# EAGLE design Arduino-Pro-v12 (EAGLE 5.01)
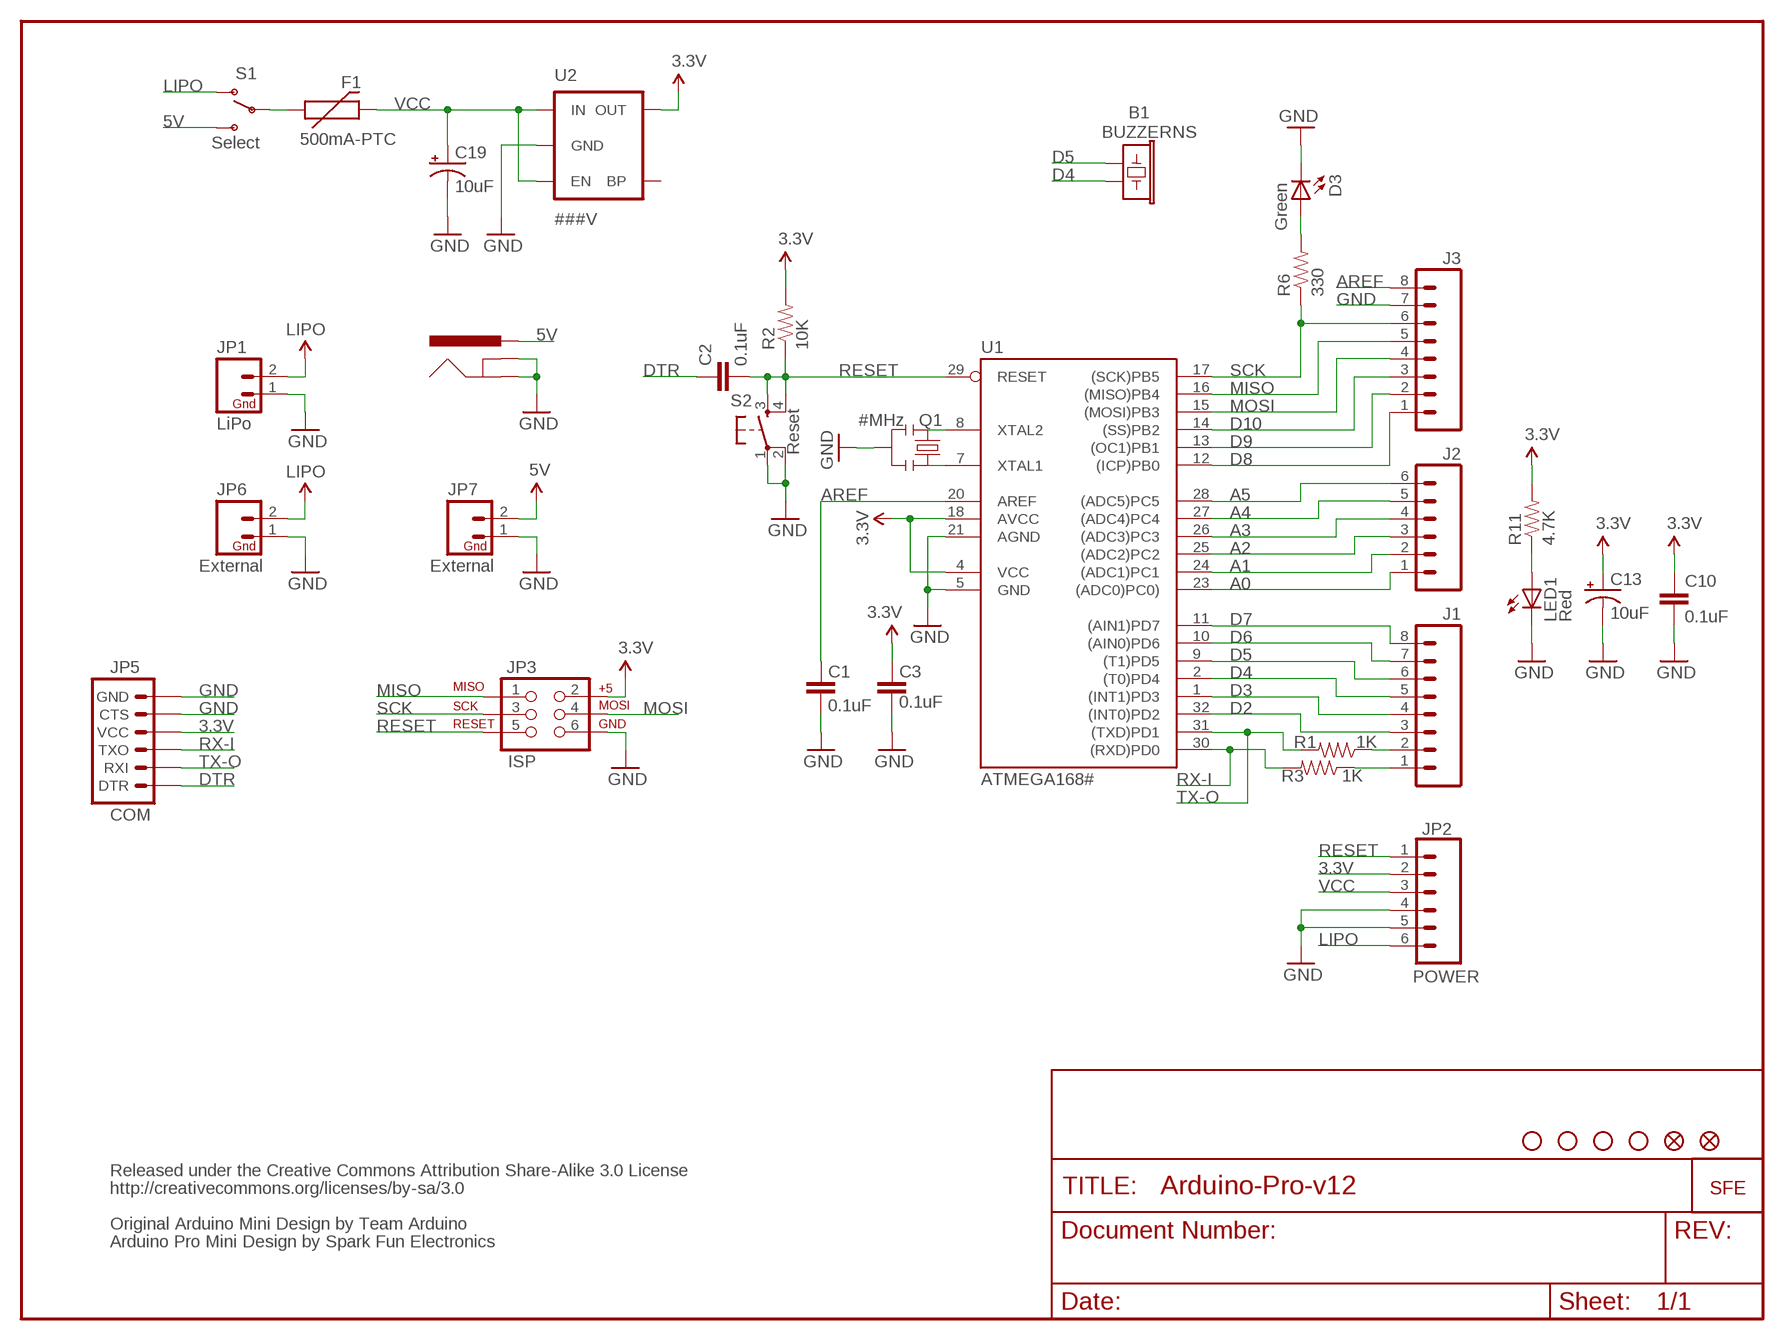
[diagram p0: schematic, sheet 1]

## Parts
B1  BUZZERNS  [BUZZER-12MM-NS]
C1  0.1uF  CAP0402  [C0402]
C2  0.1uF  CAP0402  [C0402]
C3  0.1uF  CAP0402  [C0402]
C10  0.1uF  CAP0402  [C0402]
C13  10uF  CAP_POL1206  [EIA3216]
C19  10uF  CAP_POL1206  [EIA3216]
D3  Green  LED0603  [LED-0603]
F1  500mA-PTC  PTCSMD  [PTC-1206]
J1  M08  [1X08]
J2  M06SIP  [1X06]
J3  M08  [1X08]
JP1  LiPo  M02-JST-2MM-SMT  [S2B-PH]
JP2  POWER  M06SIP  [1X06]
JP3  ISP  AVR_SPI_PRG_6PTH  [2X3]
JP4  Power Jack  POWER_JACKPTH  [POWER_JACK_PTH]
JP5  COM  ARDUINO_SERIAL_PROGRAMPTH  [1X06]
JP6  External  M02PTH  [1X02]
JP7  External  M02PTH  [1X02]
LED1  Red  LED0603  [LED-0603]
Q1  #MHz  RESONATORSMD  [RESONATOR-SMD]
R1  1K  RESISTOR0402  [C0402]
R2  10K  RESISTOR0402  [C0402]
R3  1K  RESISTOR0402  [C0402]
R6  330  RESISTOR0402  [C0402]
R11  4.7K  RESISTOR0402  [C0402]
S1  Select  SWITCH-SPSTSMD2  [SWITCH-SPST-SMD]
S2  Reset  TAC_SWITCHSND  [TACTILE_SWITCH_SMD]
U1  ATMEGA168#  AT90S4433A  [TQFP32-08]
U2  ###V  V_REG_LDOSMD  [SOT23-5]
U$1  STAND-OFF  [STAND-OFF]
U$2  FIDUCIAL1X2  [FIDUCIAL-1X2]
U$3  STAND-OFF  [STAND-OFF]
U$4  FIDUCIAL1X2  [FIDUCIAL-1X2]
U$9  STAND-OFF  [STAND-OFF]
U$10  STAND-OFF  [STAND-OFF]
U$11  LOGO-SFENEW  [SFE-NEW-WEBLOGO]

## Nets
3.3V: C3.2 C10.1 C13.A(+) JP2.2 JP3.2 JP5.4(VCC) R2.2 R11.2 U1.4(VCC) U1.18(AVCC) U2.5(OUT)
5V [vcc]: JP4.PWR JP7.2 S1.3(S)
A0: J2.1 U1.23((ADC0)PC0))
A1: J2.2 U1.24((ADC1)PC1)
A2: J2.3 U1.25((ADC2)PC2)
A3: J2.4 U1.26((ADC3)PC3)
A4: J2.5 U1.27((ADC4)PC4)
A5: J2.6 U1.28((ADC5)PC5)
AREF: C1.2 J3.8 U1.20(AREF)
D2: J1.3 U1.32((INT0)PD2)
D3: J1.4 U1.1((INT1)PD3)
D4: B1.- J1.5 U1.2((T0)PD4)
D5: B1.+ J1.6 U1.9((T1)PD5)
D6: J1.7 U1.10((AIN0)PD6)
D7: J1.8 U1.11((AIN1)PD7)
D8: J3.1 U1.12((ICP)PB0)
D9: J3.2 U1.13((OC1)PB1)
D10: J3.3 U1.14((SS)PB2)
DTR: C2.1 JP5.1(DTR)
GND [vcc]: C1.1 C3.1 C10.2 C13.C(-) C19.C(-) D3.C J3.7 JP1.1 JP2.4 JP2.5 JP3.6 JP4.GND JP4.GNDBREAK JP5.5(CTS) JP5.6(GND) JP6.1 JP7.1 LED1.C Q1.2 S2.1 S2.2 U1.5(GND) U1.21(AGND) U2.2(GND)
LIPO: JP1.2 JP2.6 JP6.2 S1.1(O)
MISO: J3.5 JP3.1 U1.16((MISO)PB4)
MOSI: J3.4 JP3.4 U1.15((MOSI)PB3)
N$3: Q1.1 U1.8(XTAL2)
N$4: Q1.3 U1.7(XTAL1)
N$7: D3.A R6.2
N$25: F1.1 S1.2(P)
N$38: LED1.A R11.1
RESET: C2.2 JP2.1 JP3.5 R2.1 S2.3 S2.4 U1.29(RESET)
RX-I: JP5.3(TXO) R3.2 U1.30((RXD)PD0)
RX-IP: J1.2 R1.1
SCK: J3.6 JP3.3 R6.1 U1.17((SCK)PB5)
TX-O: JP5.2(RXI) R1.2 U1.31((TXD)PD1)
TX-OP: J1.1 R3.1
VCC [vcc]: C19.A(+) F1.2 JP2.3 U2.1(IN) U2.3(EN)
Unconnected: U2.4(BP)

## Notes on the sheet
- Released under the Creative Commons Attribution Share-Alike 3.0 License
- http://creativecommons.org/licenses/by-sa/3.0
- Original Arduino Mini Design by Team Arduino
- Arduino Pro Mini Design by Spark Fun Electronics

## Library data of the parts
B1 = SparkFun:BUZZER: Buzzer 12mm
C1-C3 C10 = SparkFun:CAP: Capacitor
C13 C19 = SparkFun:CAP_POL: Capacitor Polarized
D3 LED1 = SparkFun:LED: LEDs
F1 = SparkFun:PTC: Resettable Fuse PTC
J1 J3 = SparkFun:M08: Header 8 Standard 8-pin 0.1" header. Use with straight break away headers (SKU : PRT-00116), right angle break away headers (PRT-00553), swiss pins (PRT-00743), machine pins (PRT-00117), and female headers (PRT-00115).
J2 JP2 = SparkFun:M06: Header 6 Standard 6-pin 0.1" header. Use with straight break away headers (SKU : PRT-00116), right angle break away headers (PRT-00553), swiss pins (PRT-00743), machine pins (PRT-00117), and female headers (PRT-00115). Molex polarized connector foot print use with SKU : PRT-08094 with associated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
JP1 JP6 JP7 = SparkFun:M02: Header 2
JP3 = SparkFun:AVR_SPI_PRG_6: AVR ISP 6 Pin This is the reduced ISP connector for AVR programming. Common on Arduino. This footprint will take up less PCB space and can be used with a 10-pin to 6-pin adapter such as SKU: BOB-08508
JP4 = SparkFun:POWER_JACK: Power Jack This is the standard 5.5mm barrel jack for power. The PTH is the most common, proven, reliable, footprint. All others are experimental. The Slot footprint only works if the mill layer is transmitted to the PCB fab house so be warned. Spark Fun Electronics SKU : PRT-00119. Mating wall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
JP5 = SparkFun:ARDUINO_SERIAL_PROGRAM
Q1 = SparkFun:RESONATOR: Resonator Small SMD resonator. This is the itty bitty 10/20MHz resonators with built in caps. CSTCE10M0G55 and CSTCE20M0V53. Footprint has been reviewed closely but hasn't been tested yet.
R1-R3 R6 R11 = SparkFun:RESISTOR: Resistor
S1 = SparkFun:SWITCH-SPST: SPST Switch Simple slide switch. Spark Fun Electronics SKU : COM-00102
S2 = SparkFun:TAC_SWITCH: Momentary Switch Button commonly used for reset or general input. Spark Fun Electronics SKU : COM-00097
U1 = atmel:AT90S4433: MICROCONTROLLER 4 Kbytes FLASH 128 bytes SRAM 256 bytes EEPROM UART 6-channel 10 bit ADC
U2 = SparkFun:V_REG_LDO: Voltage Regulator LDO Standard 150mA LDO voltage regulator in SOT-23 layout. Micrel part MIC5205. BP (by-pass) pin is used to lower output noise with 470pF cap.
U$1 U$3 U$9 U$10 = SparkFun:STAND-OFF: Stand Off
U$2 U$4 = SparkFun:FIDUCIAL: Fiducial Alignment Points
U$11 = SparkFun:LOGO-SFE: Spark Fun Electronics PCB Logo

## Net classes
0 default: width 0.203 mm
1 vcc: width 0.254 mm

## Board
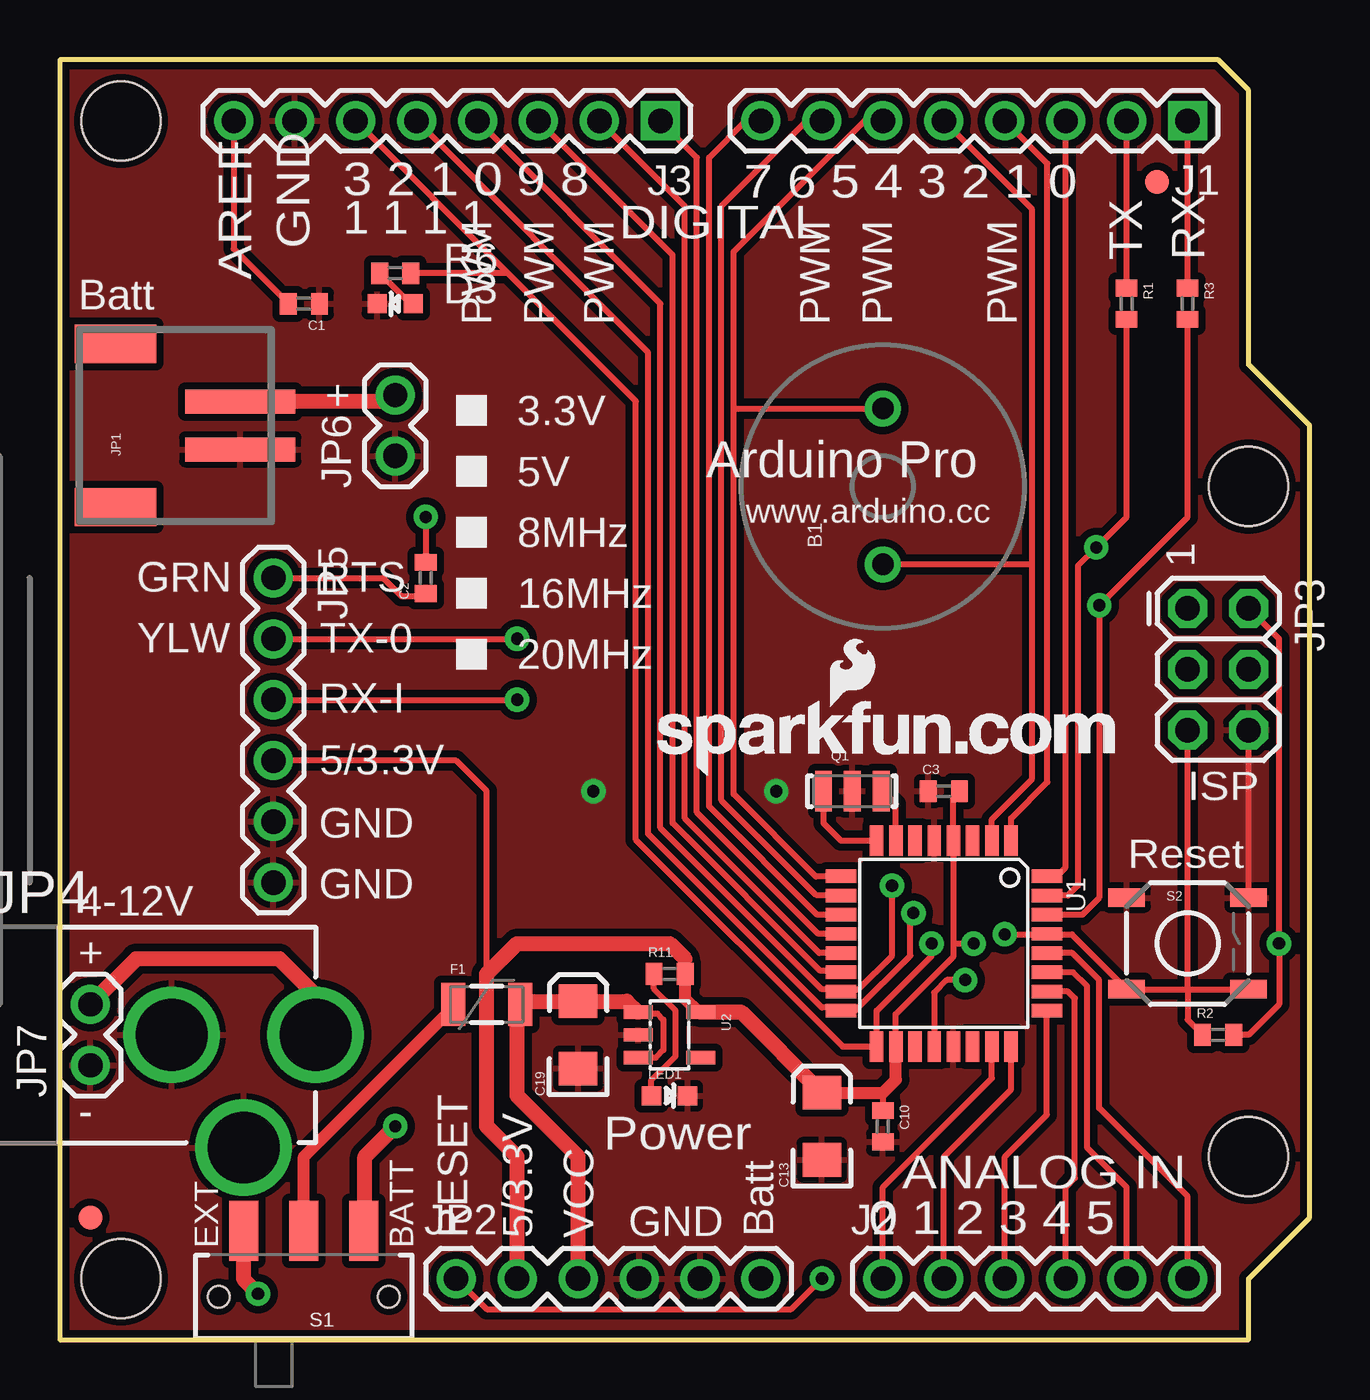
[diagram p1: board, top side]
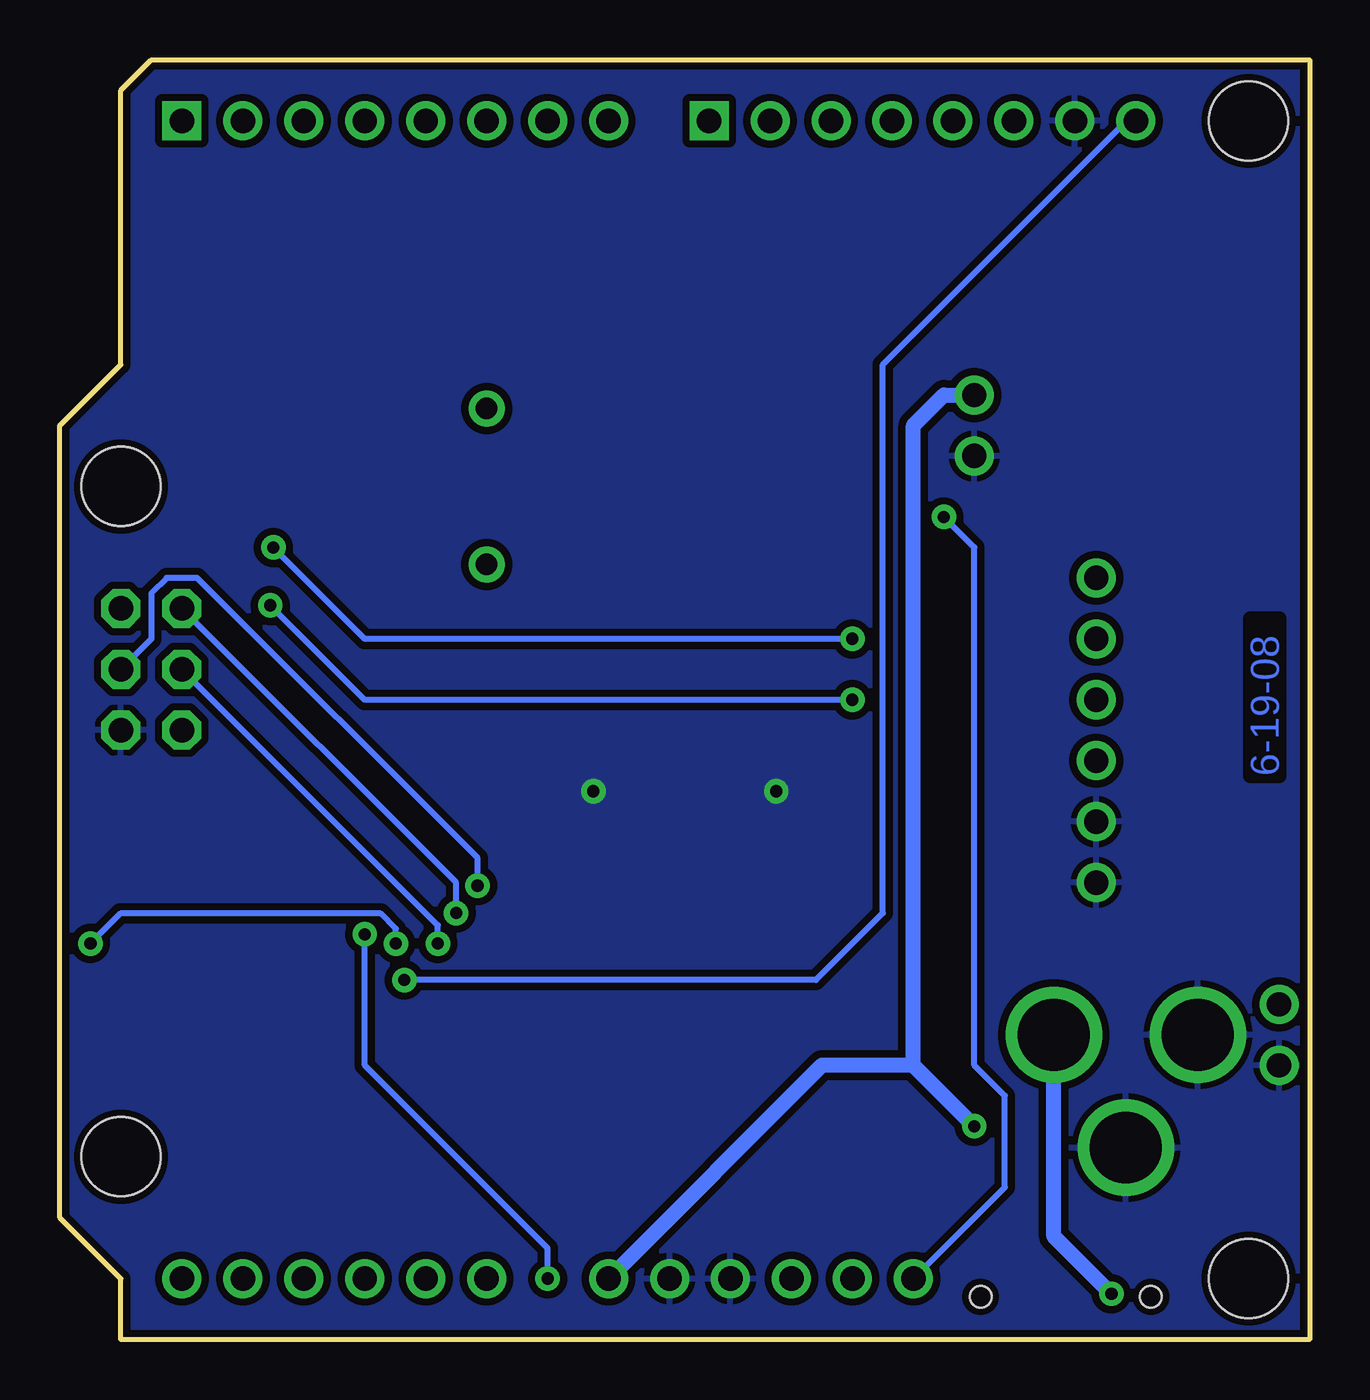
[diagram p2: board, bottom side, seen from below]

Size 52.07 x 53.34 mm. Coordinates in mm from the lower left corner, seen from the top.
Outline: 0,53.34 0,0 49.53,0 49.53,2.54 52.07,5.08 52.07,38.1 49.53,40.64 49.53,52.07 48.26,53.34 0,53.34
Copper layers (1*16): Top 0.035mm / dielectric 1.5mm / Bottom 0.035mm
Design rules "SparkFun": minimum track width 8mil, minimum drill 20mil, track to track 8mil, track to pad 8mil, pad to pad 8mil, via to via 8mil, smd to smd 8mil, copper to edge 10mil, drill to drill 8mil, minimum pad ring 12mil, minimum via ring 10mil, stop-mask expansion 4mil, vias tented up to drill 20mil, thermal gap 10mil

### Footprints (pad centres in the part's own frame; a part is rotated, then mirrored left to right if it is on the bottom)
BUZZER-12MM-NS = drill 0.9 round: + 3.25,0; - -3.25,0
C0402 = smd 0.7 x 0.9: 1 -0.65,0; 2 0.65,0
EIA3216 = smd 1.4 x 1.6: A 1.4,0; C -1.4,0
LED-0603 = smd 0.8 x 0.8: A 0,-0.75; C 0,0.75
PTC-1206 = smd 1 x 1.8: 1 -1.4,0; 2 1.4,0
1X08 = drill 1.016 square: 1 0,0 | drill 1.016 round: 2 2.54,0; 3 5.08,0; 4 7.62,0; 5 10.16,0; 6 12.7,0; 7 15.24,0; 8 17.78,0
1X06 = drill 1.016 round: 1 0,0; 2 2.54,0; 3 5.08,0; 4 7.62,0; 5 10.16,0; 6 12.7,0
S2B-PH = smd 1 x 4.6: 1 -1,-3.7; 2 1,-3.7 | smd 1.6 x 3.4: P$1 -3.4,1.5; P$2 3.4,1.5
2X3 = drill 1.016 octagon: 1 0,0; 2 0,2.54; 3 2.54,0; 4 2.54,2.54; 5 5.08,0; 6 5.08,2.54
POWER_JACK_PTH = drill 2.997 round: GND 0,7.7; GNDBREAK 4.7,10.7; PWR 0,13.7
1X02 = drill 1.016 round: 1 0,0; 2 2.54,0
RESONATOR-SMD = smd 0.7 x 1.7: 1 -1.2,0; 2 0,0; 3 1.2,0
SWITCH-SPST-SMD = smd 1.2 x 2.5: 1 -2.5,-2.75; 2 0,-2.75; 3 2.5,-2.75 | hole 0.9: -3.55,0; 3.55,0
TACTILE_SWITCH_SMD = smd 1.524 x 0.762: 1 -2.54,1.905; 2 2.54,1.905; 3 -2.54,-1.905; 4 2.54,-1.905
TQFP32-08 = smd 1.27 x 0.559: 1 -4.293,2.8; 2 -4.293,2; 3 -4.293,1.2; 4 -4.293,0.4; 5 -4.293,-0.4; 6 -4.293,-1.2; 7 -4.293,-2; 8 -4.293,-2.8; 17 4.293,-2.8; 18 4.293,-2; 19 4.293,-1.2; 20 4.293,-0.4; 21 4.293,0.4; 22 4.293,1.2; 23 4.293,2; 24 4.293,2.8 | smd 0.559 x 1.27: 9 -2.8,-4.293; 10 -2,-4.293; 11 -1.2,-4.293; 12 -0.4,-4.293; 13 0.4,-4.293; 14 1.2,-4.293; 15 2,-4.293; 16 2.8,-4.293; 25 2.8,4.293; 26 2,4.293; 27 1.2,4.293; 28 0.4,4.293; 29 -0.4,4.293; 30 -1.2,4.293; 31 -2,4.293; 32 -2.8,4.293
SOT23-5 = smd 0.55 x 1.2: 1 -0.95,-1.3; 2 0,-1.3; 3 0.95,-1.3; 4 0.95,1.3; 5 -0.95,1.3
STAND-OFF = hole 3.302: 0,0
FIDUCIAL-1X2 = smd 1 x 1: 1 0,0

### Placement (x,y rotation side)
B1  34.29,35.56 90 top
C1  10.16,43.18 180 top
C2  15.24,31.75 90 top
C3  36.83,22.86 0 top
C10  34.29,8.89 270 top
C13  31.75,8.89 90 top
C19  21.59,12.7 90 top
D3  13.97,43.18 90 top
F1  17.78,13.97 0 top
J1  46.99,50.8 180 top
J2  34.29,2.54 0 top
J3  25.02,50.8 180 top
JP1  3.81,38.1 90 top
JP2  16.51,2.54 0 top
JP3  46.99,30.48 270 top
JP4  -3.05,12.7 270 top
JP5  8.89,31.75 270 top
JP6  13.97,36.83 90 top
JP7  1.27,11.43 90 top
LED1  25.4,10.16 270 top
Q1  33.02,22.86 0 top
R1  44.45,43.18 270 top
R2  48.26,12.7 0 top
R3  46.99,43.18 270 top
R6  13.97,44.45 180 top
R11  25.4,15.24 0 top
S1  10.16,1.78 180 top
S2  46.99,16.51 0 top
U1  36.83,16.51 270 top
U2  25.4,12.7 270 top
U$1  2.54,50.8 0 top
U$2  1.27,5.08 0 top
U$3  2.54,2.54 0 top
U$4  45.72,48.26 0 top
U$9  49.53,35.56 0 top
U$10  49.53,7.62 0 top
U$11  24.89,23.5 0 top

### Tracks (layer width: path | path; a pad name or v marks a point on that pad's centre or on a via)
3.3V  (via drill 0.51)
  Top 0.254: 34.29,10.29 C10.1 | C13.A 31.75,10.16 | 26.54,13.59 26.6,13.65 26.61,13.65 U2.5 | U1.18 34.82,13.56 37.24,15.98 37.24,16.51 | U1.4 37.24,20.9 | U1.4 37.23,22.57 37.52,22.86 C3.2 | 37.24,16.51 U1.4 | JP3.2 50.8,29.21 v50.8,16.51 50.8,13.97 49.53,12.7 R2.2 | 37.24,16.51 v38.08,16.51 | JP5.4 16.51,24.13 17.78,22.86 17.78,15.24
  Top 0.508: U1.18 34.83,10.83 34.29,10.29 31.88,10.29 | 26.05,15.86 R11.2 26.04,15.24 26.04,14.22 26.61,13.65
  Top 0.635: U2.5 28.39,13.65 C13.A 31.87,10.29 31.88,10.29 | 26.05,15.86 25.4,16.51 19.05,16.51 17.78,15.24 17.78,8.89 19.05,7.62 JP2.2
  Bottom 0.254: v38.08,16.51 38.08,17.12 38.71,17.75 49.55,17.75 v50.8,16.51
5V  (via drill 0.51)
  Top 0.635: S1.3 7.66,2.5 v8.26,1.91 | JP7.2 3.17,15.88 9.14,15.88 10.67,14.35 10.67,12.7 JP4.PWR
  Bottom 0.635: JP4.PWR 10.65,4.3 v8.26,1.91
A0
  Top 0.254: U1.23 38.83,10.89 34.29,6.35 J2.1
A1
  Top 0.254: U1.24 39.63,10.42 36.83,7.62 J2.2
A2
  Top 0.254: U1.25 41.12,9.37 39.37,7.62 39.37,2.79 39.5,2.67 J2.3
A3
  Top 0.254: U1.26 42.01,14.51 42.29,14.22 42.29,6.73 41.91,6.35 J2.4
A4
  Top 0.254: U1.27 42.22,15.31 42.8,14.73 42.8,8 44.45,6.35 J2.5
A5
  Top 0.254: U1.28 42.18,16.11 43.31,14.99 43.31,9.65 46.99,5.97 J2.6
AREF  (via drill 0.51)
  Top 0.254: U1.20 36.43,14.46 36.96,14.99 v37.72,14.99 | C1.2 9.53,43.18 7.24,45.47 J3.8
  Bottom 0.254: v37.72,14.99 20.57,14.99 17.78,17.78 17.78,40.64 7.62,50.8 J3.8
D2
  Top 0.254: U1.32 41.52,19.31 41.53,19.3 41.91,19.68 J1.3
D3
  Top 0.254: U1.1 39.63,21.72 41.15,23.24 41.15,49.02 J1.4
D4
  Top 0.254: U1.2 38.83,21.68 40.51,23.37 40.51,32.26 | 40.51,32.26 40.51,47.12 J1.5 | B1.- 40.46,32.31 40.51,32.26
D5
  Top 0.254: U1.9 32.64,19.3 | U1.9 | U1.9 31.5,19.3 28.07,22.73 28.07,38.86 | 28.07,38.86 28.07,45.34 33.53,50.8 J1.6 | B1.+ 28.12,38.81 28.07,38.86
D6
  Top 0.254: U1.10 32.42,18.51 32.38,18.54 31.5,18.54 27.56,22.48 27.56,47.24 31.11,50.8 J1.7
D7
  Top 0.254: U1.11 31.57,17.71 27.05,22.23 27.05,49.28 28.57,50.8 J1.8
D8
  Top 0.254: U1.12 31.6,16.91 26.54,21.97 26.54,49.28 J3.1
D9
  Top 0.254: U1.13 31.64,16.11 26.04,21.72 26.04,47.24 J3.2
D10
  Top 0.254: J3.3 25.53,45.21 25.53,21.53 31.69,15.37 32.51,15.37 32.51,15.34 U1.14
DTR
  Top 0.254: JP5.1 13.46,31.75 14.22,30.99 14.99,30.99 15.11,31.11 15.13,31.1 C2.1
GND  (via drill 0.51)
  Top 0.254: S2.2 JP3.6
  other vias: 29.84,22.86 22.23,22.86
  pour Top (isolate 0.305): 0,53.34 52.07,53.34 52.07,0 0,0
  pour Bottom (isolate 0.305): 0,53.34 52.07,53.34 52.07,0 0,0
LIPO  (via drill 0.51)
  Top 0.635: JP1.2 13.7,39.1 JP6.2 | S1.1 12.66,4.49 12.7,4.45 12.7,7.62 v13.97,8.89
  Bottom 0.635: JP6.2 15.24,39.37 16.51,38.1 16.51,11.43 | 16.51,11.43 20.32,11.43 JP2.6 | v13.97,8.89 16.51,11.43
MISO  (via drill 0.51)
  Top 0.254: J3.5 24.51,41.15 24.51,21.08 31.75,13.84 32.64,13.84 32.54,13.74 U1.16 | U1.16 | U1.16 32.63,13.71 32.64,13.72 33.15,13.72 35.43,16 35.43,17.65 v35.56,17.78
  Bottom 0.254: JP3.1 35.56,19.05 v35.56,17.78
MOSI  (via drill 0.51)
  Top 0.254: J3.4 25.02,43.18 25.02,21.34 31.75,14.61 32.51,14.61 32.54,14.58 U1.15 | 32.64,14.48 32.57,14.48 U1.15 | v34.67,18.92 34.67,16 33.27,14.61 32.77,14.61 32.64,14.48 | 32.64,14.48 32.61,14.51 U1.15
  Bottom 0.254: JP3.4 48.26,29.21 48.26,31.11 47.62,31.75 46.35,31.75 34.67,20.07 v34.67,18.92
N$3
  Top 0.254: U1.8 32.54,20.8 31.82,21.52 Q1.1
N$4
  Top 0.254: Q1.3 34.29,22.86 34.83,22.32 U1.7
N$7
  Top 0.254: D3.A 14.61,43.18 13.34,44.45 R6.2
N$25
  Top 0.508: 16.51,13.97 10.16,7.62 S1.2 10.16,4.45
  Top 0.635: 16.51,13.97 F1.1
N$38
  Top 0.254: R11.1 24.75,14.62 25.65,13.72 25.65,11.81 24.64,10.79 24.64,10.16 LED1.A
RESET  (via drill 0.51)
  Top 0.254: S2.4 49.66,14.61 | JP2.1 17.78,1.27 30.48,1.27 v31.75,2.54 | v39.37,16.89 41.02,16.89 41.04,16.91 U1.29 41.26,16.91 41.27,16.89 42.16,16.89 S2.3 46.99,14.61 | S2.4 49.4,14.61 | 46.99,14.61 JP3.5 | R2.1 47.62,12.7 46.99,13.34 46.99,14.61 | 46.99,14.61 S2.4 | v15.24,34.29 C2.2
  Bottom 0.254: v39.37,16.89 39.37,11.43 31.75,3.81 v31.75,2.54 | JP2.1 12.7,6.35 12.7,10.16 13.97,11.43 13.97,33.02 v15.24,34.29
RX-I  (via drill 0.51)
  Top 0.254: U1.30 42.6,17.71 43.31,18.41 v43.31,30.61 46.99,34.29 R3.2 | JP5.3 v19.05,26.67
  Bottom 0.254: v19.05,26.67 39.37,26.67 v43.31,30.61
RX-IP
  Top 0.254: R1.1 J1.2
SCK  (via drill 0.51)
  Top 0.254: 18.67,44.45 24,39.12 24,20.83 32.61,12.22 U1.17 34.03,13.71 36.32,16 v36.32,16.51 | 18.67,44.45 J3.6 | 14.62,44.47 R6.1 18.67,44.45
  Bottom 0.254: v36.32,16.51 36.32,17.27 JP3.3
TX-O  (via drill 0.51)
  Top 0.254: U1.31 42.01,18.51 42.42,18.92 42.42,32.26 v43.18,33.02 44.45,34.29 R1.2 | JP5.2 v19.05,29.21
  Bottom 0.254: v19.05,29.21 39.37,29.21 v43.18,33.02
TX-OP
  Top 0.254: R3.1 J1.1
VCC
  Top 0.254: U2.3 24.83,11.75 25.15,12.06 25.15,13.34 24.89,13.59 24.13,13.59 24.1,13.62 U2.1
  Top 0.635: 19.05,13.97 19.18,14.1 C19.A 23.62,14.1 24.07,13.65 U2.1 | JP2.3 21.59,7.62 19.05,10.16 19.05,13.97 | 19.05,13.97 F1.2

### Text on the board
Bottom: 6-19-08
tPlace: Released under the Creative Commons Attribution Share-Alike 3.0 License | http://creativecommons.org/licenses/by-sa/3.0 | 3 2 1 0 9 8 | 7 6 5 4 3 2 1 0 | 1 1 1 1 | DIGITAL | GND | TX | RX | AREF | Batt | PWM | PWM | PWM | PWM | PWM | PWM | + | 3.3V | - | 5V | Arduino Pro | www.arduino.cc | 8MHz | 1 | GRN | RTS | 16MHz | YLW | TX-0 | 20MHz | RX-I | 5/3.3V | ISP | GND | Reset | 4-12V | GND | + | - | Power | ANALOG IN | EXT | BATT | RESET | 5/3.3V | VCC | GND | Batt | 0 1 2 3 4 5
tValues: Arduino Pro | DNP | DNP | Production: DNP | DNP | JST-Right Angle | Production: DNP | Proto: 2x3 male header up | Right-angle 6-pin | DNP | DNP | DNP | DNP | DNP | DNP | Right-angle slide switch | Depending on the flavor, populate: | 8MHz Resonator/3.3V Regulator/ATmega168V | 16MHz Resonator/5V Regulator/ATmega168 | 20MHz Resonator/5V Regulator/ATmega168 | Mark the white boxes accordingly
